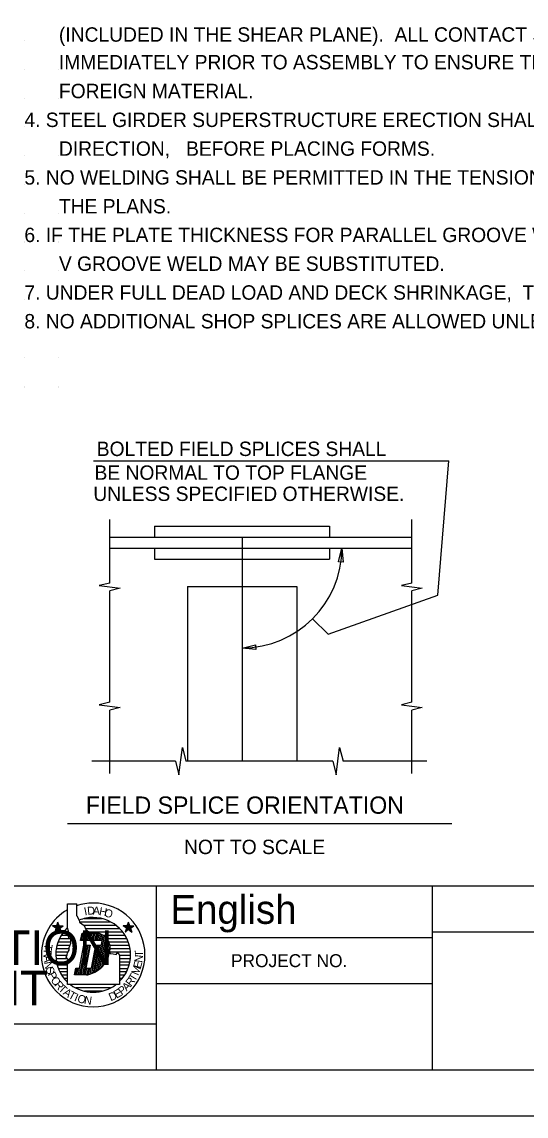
# Model space of a CAD drawing. Extents: x 0 to 47.8, y 0 to 23.5.
# Drawn here: x 17.79 to 23.27, y 0 to 11.88 of the extents above; entities that cross this region are included whole.
import ezdxf

# ---------------------------------------------------------------- set-up
doc = ezdxf.new("R2010")
doc.units = 0
for name, color, linetype in [('BORDER_ANNO_Cutsheet', 7, 'Continuous'), ('BRDG_ANNO_Anno-Sheet', 7, 'Continuous'), ('BRDG_ANNO_General-Notes', 7, 'Continuous'), ('BRDG_BASE_Active-Point', 7, 'Continuous'), ('BRDG_BASE_Hidden-Line', 7, 'Continuous'), ('BRDG_BASE_Obj-Line', 7, 'Continuous')]:
    doc.layers.add(name, color=color, linetype=linetype)

msp = doc.modelspace()

# ---------------------------------------------------------------- linework, layer by layer
at = {"layer": 'BORDER_ANNO_Cutsheet'}
msp.add_lwpolyline([(0, 22), (34, 22), (34, 0), (0, 0)], close=True, dxfattribs=at)
at = {"layer": 'BRDG_ANNO_Anno-Sheet'}
for p, q in [((1.5, 2.5), (19.25, 2.5)), ((19.25, 0.5), (19.25, 2.5)), ((19.25, 2.5), (33.5, 2.5)), ((22.25, 0.5), (22.25, 2.5)), ((18.284, 2.042), (18.284, 2.303)), ((18.284, 2.303), (18.383, 2.303)), ((18.383, 2.173), (18.383, 2.303)), ((18.383, 2.173), (18.409, 2.126)), ((18.465, 2.144), (18.658, 2.144)), ((18.201, 2.04), (18.122, 2.066)), ((18.166, 2.066), (18.122, 2.066)), ((18.157, 2.04), (18.122, 2.066)), ((18.193, 2.066), (18.144, 1.998)), ((18.157, 2.04), (18.144, 1.998)), ((18.179, 2.024), (18.144, 1.998)), ((18.157, 2.04), (18.237, 2.066)), ((18.166, 2.066), (18.179, 2.107)), ((18.166, 2.066), (18.215, 1.998)), ((18.179, 2.024), (18.179, 2.107)), ((18.193, 2.066), (18.179, 2.107)), ((18.179, 2.024), (18.215, 1.998)), ((18.193, 2.066), (18.237, 2.066)), ((18.201, 2.04), (18.237, 2.066)), ((18.201, 2.04), (18.215, 1.998)), ((18.274, 2.036), (18.286, 2.036)), ((18.294, 2.006), (18.284, 2.042)), ((18.409, 2.126), (18.414, 2.105)), ((18.414, 2.105), (18.466, 2.069)), ((18.417, 2.108), (18.751, 2.108)), ((18.465, 2.072), (18.807, 2.072)), ((18.466, 2.069), (18.482, 2.027)), ((18.479, 2.036), (18.851, 2.036)), ((18.482, 2.027), (18.534, 1.986)), ((18.968, 2.04), (18.888, 2.066)), ((18.924, 2.04), (18.888, 2.066)), ((18.932, 2.066), (18.888, 2.066)), ((18.959, 2.066), (18.91, 1.998)), ((18.924, 2.04), (18.91, 1.998)), ((18.946, 2.024), (18.91, 1.998)), ((18.924, 2.04), (19.002, 2.066)), ((18.932, 2.066), (18.946, 2.107)), ((18.932, 2.066), (18.981, 1.998)), ((18.946, 2.024), (18.946, 2.107)), ((18.959, 2.066), (18.946, 2.107)), ((18.946, 2.024), (18.981, 1.998)), ((18.959, 2.066), (19.002, 2.066)), ((18.968, 2.04), (19.002, 2.066)), ((18.968, 2.04), (18.981, 1.998)), ((18.197, 1.928), (18.298, 1.928)), ((18.217, 1.964), (18.293, 1.964)), ((18.242, 2.001), (18.294, 2.001)), ((18.294, 1.975), (18.294, 2.006)), ((18.294, 1.949), (18.294, 1.975)), ((18.3, 1.928), (18.294, 1.949)), ((18.321, 1.917), (18.3, 1.928)), ((18.321, 1.891), (18.321, 1.917)), ((18.425, 1.907), (18.441, 1.986)), ((18.661, 1.907), (18.425, 1.907)), ((18.439, 1.907), (18.454, 1.986)), ((18.441, 1.986), (18.613, 1.986)), ((18.455, 1.907), (18.47, 1.986)), ((18.471, 1.907), (18.486, 1.986)), ((18.487, 1.907), (18.502, 1.986)), ((18.502, 1.907), (18.517, 1.986)), ((18.516, 2.001), (18.883, 2.001)), ((18.519, 1.907), (18.533, 1.986)), ((18.534, 1.907), (18.549, 1.986)), ((18.551, 1.907), (18.565, 1.986)), ((18.566, 1.907), (18.581, 1.986)), ((18.582, 1.907), (18.597, 1.986)), ((18.598, 1.907), (18.613, 1.986)), ((18.599, 1.574), (18.672, 1.962)), ((18.614, 1.907), (18.628, 1.981)), ((18.617, 1.586), (18.686, 1.952)), ((18.63, 1.907), (18.643, 1.977)), ((18.636, 1.601), (18.699, 1.939)), ((18.646, 1.907), (18.657, 1.97)), ((18.652, 1.855), (18.661, 1.907)), ((18.656, 1.619), (18.712, 1.924)), ((18.669, 1.964), (18.907, 1.964)), ((18.676, 1.64), (18.725, 1.906)), ((18.71, 1.928), (18.927, 1.928)), ((19.25, 1.938), (22.25, 1.938)), ((22.25, 2), (30.25, 2)), ((18.157, 1.784), (18.291, 1.784)), ((18.162, 1.821), (18.298, 1.821)), ((18.171, 1.856), (18.311, 1.856)), ((18.181, 1.892), (18.319, 1.892)), ((18.284, 1.772), (18.3, 1.803)), ((18.3, 1.829), (18.31, 1.85)), ((18.3, 1.803), (18.3, 1.829)), ((18.31, 1.85), (18.321, 1.876)), ((18.321, 1.876), (18.321, 1.891)), ((18.414, 1.605), (18.461, 1.855)), ((18.416, 1.532), (18.477, 1.855)), ((18.433, 1.532), (18.493, 1.855)), ((18.448, 1.532), (18.509, 1.855)), ((18.461, 1.855), (18.53, 1.855)), ((18.464, 1.532), (18.525, 1.855)), ((18.53, 1.855), (18.483, 1.605)), ((18.544, 1.605), (18.591, 1.855)), ((18.547, 1.547), (18.604, 1.855)), ((18.564, 1.555), (18.62, 1.855)), ((18.581, 1.563), (18.636, 1.855)), ((18.591, 1.855), (18.652, 1.855)), ((18.697, 1.669), (18.737, 1.882)), ((18.722, 1.718), (18.746, 1.845)), ((18.732, 1.892), (18.943, 1.892)), ((18.742, 1.784), (18.968, 1.784)), ((18.744, 1.856), (18.954, 1.856)), ((18.747, 1.821), (18.962, 1.821)), ((18.156, 1.748), (18.277, 1.748)), ((18.158, 1.712), (18.281, 1.712)), ((18.163, 1.676), (18.298, 1.676)), ((18.269, 1.725), (18.279, 1.751)), ((18.284, 1.709), (18.269, 1.725)), ((18.279, 1.751), (18.284, 1.772)), ((18.294, 1.694), (18.284, 1.709)), ((18.284, 1.652), (18.3, 1.667)), ((18.3, 1.683), (18.294, 1.694)), ((18.3, 1.667), (18.3, 1.683)), ((18.741, 1.777), (18.748, 1.766)), ((18.748, 1.766), (18.779, 1.761)), ((18.779, 1.761), (18.811, 1.756)), ((18.811, 1.756), (18.826, 1.777)), ((18.826, 1.777), (18.847, 1.746)), ((18.845, 1.748), (18.969, 1.748)), ((18.847, 1.746), (18.847, 1.427)), ((18.847, 1.676), (18.962, 1.676)), ((18.848, 1.712), (18.967, 1.712)), ((18.171, 1.641), (18.284, 1.641)), ((18.184, 1.604), (18.282, 1.604)), ((18.199, 1.568), (18.282, 1.568)), ((18.284, 1.427), (18.284, 1.652)), ((18.359, 1.532), (18.373, 1.605)), ((18.369, 1.532), (18.383, 1.605)), ((18.373, 1.605), (18.414, 1.605)), ((18.385, 1.532), (18.399, 1.605)), ((18.401, 1.532), (18.414, 1.605)), ((18.48, 1.532), (18.494, 1.605)), ((18.483, 1.605), (18.544, 1.605)), ((18.496, 1.532), (18.51, 1.605)), ((18.513, 1.537), (18.526, 1.605)), ((18.53, 1.542), (18.541, 1.605)), ((18.847, 1.641), (18.954, 1.641)), ((18.847, 1.604), (18.941, 1.604)), ((18.847, 1.568), (18.925, 1.568)), ((18.22, 1.532), (18.283, 1.532)), ((18.246, 1.496), (18.282, 1.496)), ((18.277, 1.461), (18.284, 1.461)), ((18.847, 1.427), (18.284, 1.427)), ((18.492, 1.532), (18.359, 1.532)), ((18.847, 1.532), (18.905, 1.532)), ((18.847, 1.496), (18.88, 1.496)), ((19.25, 1.438), (22.25, 1.438)), ((18.751, 1.391), (18.372, 1.391)), ((18.659, 1.356), (18.468, 1.356)), ((14, 1), (19.25, 1))]:
    msp.add_line(p, q, dxfattribs=at)
msp.add_lwpolyline([(1.5, 21.5), (33.5, 21.5), (33.5, 0.5), (1.5, 0.5)], close=True, dxfattribs=at)
for centre, radius, start, end in [((18.562, 1.75), 0.563, 90, 108.596), ((18.562, 1.75), 0.563, 0, 90), ((18.562, 1.75), 0.563, 119.6331, 180), ((18.562, 1.75), 0.406, 90, 112.1452), ((18.562, 1.75), 0.406, 0, 90), ((18.562, 1.75), 0.406, 133.1926, 180), ((18.583, 1.824), 0.164, 343.4981, 79.7362), ((18.562, 1.75), 0.563, 180, 270), ((18.562, 1.75), 0.406, 180.2644, 226.7946), ((18.435, 1.838), 0.312, 280.6479, 348.7719), ((18.562, 1.75), 0.563, 270, 0), ((18.562, 1.75), 0.406, 314.427, 0), ((18.562, 1.75), 0.406, 232.5658, 270), ((18.562, 1.75), 0.406, 270, 307.4536)]:
    msp.add_arc(centre, radius, start, end, dxfattribs=at)
at = {"layer": 'BRDG_ANNO_General-Notes'}
for p, q in [((18.564, 7.113), (22.427, 7.113)), ((22.306, 5.653), (22.427, 7.113)), ((21.227, 6.018), (21.264, 6.166)), ((21.264, 6.166), (21.277, 6.014)), ((21.277, 6.014), (21.227, 6.018)), ((21.115, 5.23), (22.306, 5.653)), ((21.115, 5.23), (20.946, 5.398)), ((20.179, 5.081), (20.327, 5.116)), ((20.327, 5.116), (20.33, 5.066)), ((20.33, 5.066), (20.179, 5.081)), ((18.285, 3.175), (22.459, 3.175))]:
    msp.add_line(p, q, dxfattribs=at)
msp.add_arc((20.179, 6.166), 1.085, 270, 0, dxfattribs=at)
at = {"layer": 'BRDG_BASE_Active-Point'}
for p, q in [((17.815, 11.676), (17.815, 11.676)), ((17.815, 11.362), (17.815, 11.362)), ((18.19, 11.362), (18.19, 11.362)), ((17.815, 11.05), (17.815, 11.05)), ((18.19, 11.05), (18.19, 11.05)), ((17.815, 10.737), (17.815, 10.737)), ((18.19, 10.737), (18.19, 10.737)), ((17.815, 10.424), (17.815, 10.424)), ((18.19, 10.424), (18.19, 10.424)), ((17.815, 10.112), (17.815, 10.112)), ((18.19, 10.112), (18.19, 10.112)), ((17.815, 9.798), (17.815, 9.798)), ((18.19, 9.798), (18.19, 9.798)), ((17.815, 9.488), (17.815, 9.488)), ((17.815, 9.487), (17.815, 9.487)), ((17.815, 9.487), (17.815, 9.487)), ((18.19, 9.488), (18.19, 9.488)), ((18.19, 9.487), (18.19, 9.487)), ((18.19, 9.487), (18.19, 9.487)), ((17.815, 9.175), (17.815, 9.175)), ((17.815, 9.175), (17.815, 9.175)), ((17.815, 9.174), (17.815, 9.174)), ((18.19, 9.175), (18.19, 9.175)), ((18.19, 9.175), (18.19, 9.175)), ((18.19, 9.174), (18.19, 9.174)), ((17.815, 8.862), (17.815, 8.862)), ((18.19, 8.862), (18.19, 8.862)), ((17.815, 8.549), (17.815, 8.549)), ((18.19, 8.549), (18.19, 8.549)), ((17.815, 8.236), (17.815, 8.236)), ((18.19, 8.236), (18.19, 8.236)), ((17.815, 7.924), (17.815, 7.924)), ((17.815, 7.911), (17.815, 7.911)), ((18.19, 7.924), (18.19, 7.924)), ((18.19, 7.911), (18.19, 7.911))]:
    msp.add_line(p, q, dxfattribs=at)
at = {"layer": 'BRDG_BASE_Hidden-Line'}
for p, q in [((20.179, 6.166), (20.179, 6.047)), ((20.179, 5.75), (20.179, 3.851))]:
    msp.add_line(p, q, dxfattribs=at)
at = {"layer": 'BRDG_BASE_Obj-Line'}
for p, q in [((18.742, 5.786), (18.742, 6.475)), ((22.022, 5.786), (22.022, 6.475)), ((19.229, 6.403), (21.129, 6.403)), ((19.229, 6.403), (19.229, 6.286)), ((21.129, 6.403), (21.129, 6.286)), ((18.742, 6.284), (22.022, 6.284)), ((20.179, 6.284), (20.179, 6.166)), ((18.742, 6.166), (22.022, 6.166)), ((19.229, 6.167), (19.229, 6.047)), ((21.129, 6.163), (21.129, 6.047)), ((19.229, 6.047), (21.129, 6.047)), ((20.179, 6.047), (20.179, 5.75)), ((18.742, 5.786), (18.629, 5.758)), ((18.629, 5.758), (18.854, 5.73)), ((18.854, 5.73), (18.742, 5.702)), ((18.742, 4.492), (18.742, 5.702)), ((19.585, 5.75), (19.585, 3.851)), ((19.585, 5.75), (20.773, 5.75)), ((20.773, 5.75), (20.773, 3.851)), ((22.022, 5.786), (21.91, 5.758)), ((21.91, 5.758), (22.135, 5.73)), ((22.135, 5.73), (22.022, 5.702)), ((22.022, 4.492), (22.022, 5.702)), ((18.742, 4.492), (18.629, 4.464)), ((18.629, 4.464), (18.854, 4.436)), ((18.854, 4.436), (18.742, 4.408)), ((18.742, 3.719), (18.742, 4.408)), ((22.022, 4.492), (21.91, 4.464)), ((21.91, 4.464), (22.135, 4.436)), ((22.135, 4.436), (22.022, 4.408)), ((22.022, 3.719), (22.022, 4.408)), ((19.494, 3.703), (19.531, 4)), ((19.531, 4), (19.568, 3.851)), ((21.202, 3.703), (21.239, 4)), ((21.239, 4), (21.276, 3.851)), ((19.457, 3.851), (18.547, 3.851)), ((19.457, 3.851), (19.494, 3.703)), ((21.165, 3.851), (19.568, 3.851)), ((21.165, 3.851), (21.202, 3.703)), ((22.186, 3.851), (21.276, 3.851))]:
    msp.add_line(p, q, dxfattribs=at)

# ---------------------------------------------------------------- texts
at = {"layer": 'BRDG_ANNO_Anno-Sheet'}
for s, height, p in [('English', 0.3125, (19.401, 2.087)), ('TRANSPORTATION', 0.375, (14.147, 1.641)), ('PROJECT NO.', 0.14062, (20.059, 1.617)), ('DEPARTMENT', 0.375, (14.619, 1.203))]:
    msp.add_text(s, height=height, dxfattribs=at).set_placement(p)
for s, rotation, p in [('I', 11.9519, (18.472, 2.178)), ('D', 5.2118, (18.501, 2.184)), ('A', 357.8718, (18.557, 2.188)), ('H', 349.6318, (18.622, 2.184)), ('O', 342.1917, (18.674, 2.173)), ('R', 266.0275, (18.026, 1.807)), ('T', 259.4265, (18.038, 1.876)), ('T', 90.4926, (19.102, 1.729)), ('A', 273.764, (18.023, 1.741)), ('N', 280.3758, (18.029, 1.671)), ('E', 75.6105, (19.079, 1.597)), ('N', 83.1932, (19.095, 1.663)), ('S', 287.9279, (18.043, 1.604)), ('P', 295.4976, (18.066, 1.541)), ('T', 59.0362, (19.014, 1.455)), ('M', 67.7139, (19.051, 1.521)), ('O', 302.6446, (18.096, 1.48)), ('R', 309.9079, (18.134, 1.422)), ('T', 317.1211, (18.177, 1.371)), ('A', 45, (18.926, 1.351)), ('R', 52.3344, (18.974, 1.401)), ('A', 324.6375, (18.228, 1.326)), ('T', 331.7503, (18.284, 1.287)), ('I', 337.0213, (18.349, 1.254)), ('O', 343.3287, (18.383, 1.241)), ('D', 22.9887, (18.753, 1.246)), ('E', 30.5476, (18.816, 1.274)), ('P', 37.6656, (18.873, 1.309)), ('N', 351.6598, (18.459, 1.22))]:
    msp.add_text(s, height=0.0869, rotation=rotation, dxfattribs=at).set_placement(p)
at = {"layer": 'BRDG_ANNO_General-Notes'}
for s, height, p in [('(INCLUDED IN THE SHEAR PLANE).  ALL CONTACT SURFACES OF THE BOLTED CONNECTIONS SHALL BE FIELD INSPECTED', 0.15625, (18.19, 11.662)), ('IMMEDIATELY PRIOR TO ASSEMBLY TO ENSURE THAT THE SURFACES ARE FREE OF ALL MILL SCALE,  DIRT,  ROAD OIL,  AND OTHER', 0.15625, (18.19, 11.362)), ('FOREIGN MATERIAL.', 0.15625, (18.19, 11.049)), ('4. STEEL GIRDER SUPERSTRUCTURE ERECTION SHALL BE COMPLETE FOR EACH SPAN AND TWO ADJACENT SPANS IN EACH', 0.15625, (17.815, 10.736)), ('DIRECTION,   BEFORE PLACING FORMS.', 0.15625, (18.19, 10.424)), ('5. NO WELDING SHALL BE PERMITTED IN THE TENSION OR STRESS REVERSAL ZONES OF THE GIRDERS EXCEPT AS SHOWN ON', 0.15625, (17.815, 10.111)), ('THE PLANS.', 0.1562, (18.19, 9.798)), ('6. IF THE PLATE THICKNESS FOR PARALLEL GROOVE WELD EXCEEDS THE PREQUALIFIED THICKNESS LISTED IN D1.5 THEN', 0.15625, (17.815, 9.487)), ('V GROOVE WELD MAY BE SUBSTITUTED.', 0.15625, (18.19, 9.175)), ('7. UNDER FULL DEAD LOAD AND DECK SHRINKAGE,  THE GIRDER WEB SHALL BE VERTICAL THE FULL LENGTH OF THE GIRDER.', 0.15625, (17.815, 8.862)), ('8. NO ADDITIONAL SHOP SPLICES ARE ALLOWED UNLESS APPROVED BY THE ENGINEER.', 0.15625, (17.815, 8.55)), ('BOLTED FIELD SPLICES SHALL', 0.15625, (18.601, 7.165)), ('BE NORMAL TO TOP FLANGE', 0.15625, (18.577, 6.907)), ('UNLESS SPECIFIED OTHERWISE. ', 0.15625, (18.564, 6.677)), ('FIELD SPLICE ORIENTATION', 0.1875, (18.482, 3.282)), ('NOT TO SCALE', 0.15625, (19.549, 2.844))]:
    msp.add_text(s, height=height, dxfattribs=at).set_placement(p)

doc.saveas('drawing.dxf')
